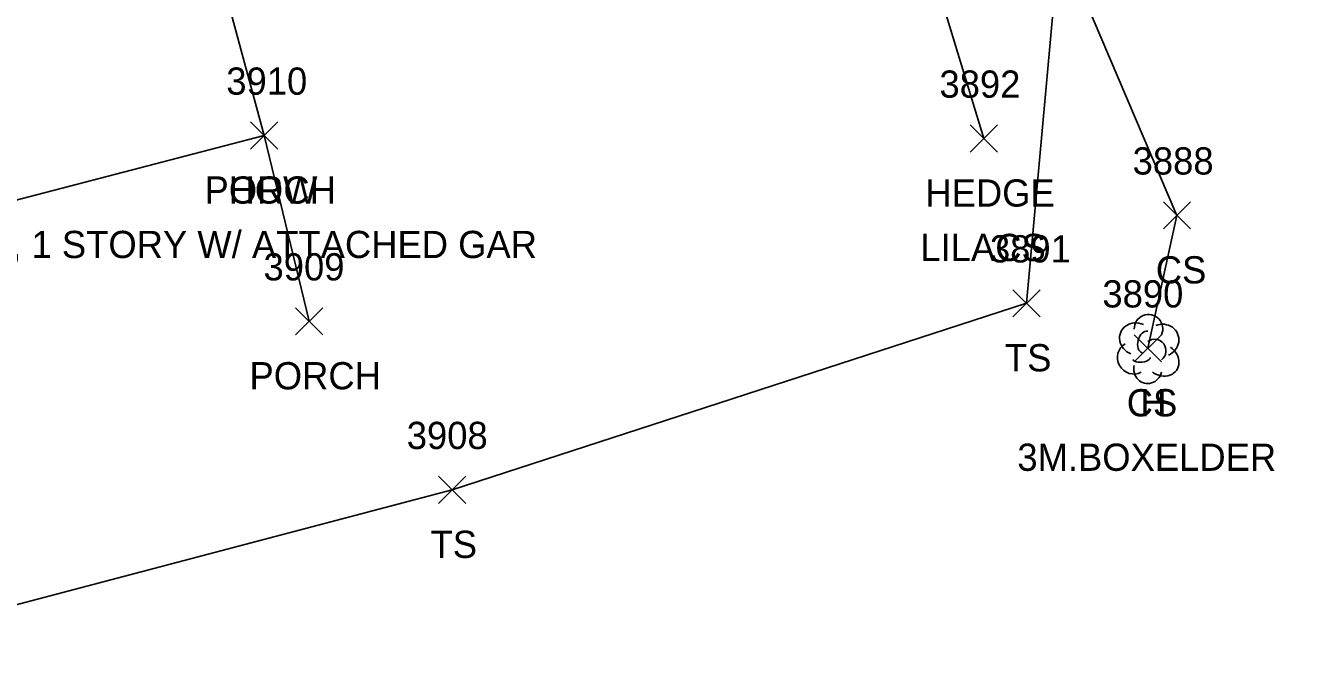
# Model space of a CAD drawing. Extents: x 1520648 to 1523413, y 732854 to 735518.
# Drawn here: x 1521101.5 to 1521194.8, y 733381.9 to 733427.9 of the extents above; entities that cross this region are included whole.
import ezdxf

# ---------------------------------------------------------------- set-up
doc = ezdxf.new("R2010")
doc.units = 0
for name, color, linetype in [('L_A', 7, 'Continuous'), ('L_C', 7, 'Continuous'), ('L_I', 7, 'Continuous'), ('L_TIC', 7, 'Continuous'), ('LAHR', 7, 'Continuous'), ('LBC', 7, 'Continuous'), ('LBF', 7, 'Continuous'), ('LELB', 7, 'Continuous'), ('LTD', 7, 'Continuous')]:
    doc.layers.add(name, color=color, linetype=linetype)

msp = doc.modelspace()

# ---------------------------------------------------------------- linework, layer by layer
at = {"layer": 'L_TIC'}
for points in [[(1521118.013, 733418.775), (1521120.013, 733420.775)], [(1521120.013, 733418.775), (1521118.013, 733420.775)], [(1521118.013, 733418.775), (1521120.013, 733420.775)], [(1521120.013, 733418.775), (1521118.013, 733420.775)], [(1521118.013, 733418.775), (1521120.013, 733420.775)], [(1521120.013, 733418.775), (1521118.013, 733420.775)], [(1521170.906, 733418.556), (1521172.906, 733420.556)], [(1521172.906, 733418.556), (1521170.906, 733420.556)], [(1521185.103, 733412.911), (1521187.103, 733414.911)], [(1521187.103, 733412.911), (1521185.103, 733414.911)], [(1521174.05, 733406.453), (1521176.05, 733408.453)], [(1521176.05, 733406.453), (1521174.05, 733408.453)], [(1521121.318, 733405.132), (1521123.318, 733407.132)], [(1521123.318, 733405.132), (1521121.318, 733407.132)], [(1521182.967, 733403.146), (1521184.967, 733405.146)], [(1521184.967, 733403.146), (1521182.967, 733405.146)], [(1521131.836, 733392.748), (1521133.836, 733394.748)], [(1521133.836, 733392.748), (1521131.836, 733394.748)]]:
    msp.add_lwpolyline(points, dxfattribs=at)
at = {"layer": 'LAHR'}
msp.add_lwpolyline([(1521171.906, 733419.556), (1521165.595, 733440.326)], dxfattribs=at)
at = {"layer": 'LBC'}
for points in [[(1521119.013, 733419.775), (1521112.234, 733444.881), (1521096.471, 733440.713), (1521093.138, 733452.827), (1521091.886, 733457.266), (1521088.382, 733469.903), (1521080.446, 733467.758), (1521080.092, 733468.783), (1521069.257, 733465.848), (1521065.514, 733464.895), (1521054.232, 733461.833), (1521062.279, 733432.129), (1521080.36, 733436.15)], [(1521119.013, 733419.775), (1521093.156, 733413.057), (1521090.415, 733422.521)]]:
    msp.add_lwpolyline(points, dxfattribs=at)
at = {"layer": 'LBF'}
msp.add_lwpolyline([(1521122.318, 733406.132), (1521119.013, 733419.775)], dxfattribs=at)
at = {"layer": 'LELB'}
for points in [[(1521156.262, 733492.333), (1521160.076, 733479.636), (1521169.187, 733456.994), (1521177.459, 733434.149), (1521186.103, 733413.911), (1521183.967, 733404.146)], [(1521252.104, 733415.19), (1521228.37, 733429.385), (1521182.522, 733453.142), (1521177.459, 733434.149), (1521175.05, 733407.453), (1521132.836, 733393.748), (1521088.037, 733381.942)]]:
    msp.add_lwpolyline(points, dxfattribs=at)
at = {"layer": 'LTD'}
msp.add_line((1521183.967, 733404.146), (1521183.967, 733404.146), dxfattribs=at)
msp.add_line((1521183.967, 733404.146), (1521183.967, 733404.146), dxfattribs=at)
msp.add_arc((1521184.014, 733405.58), 1.047, 335.52715, 180.95627, dxfattribs=at)
for centre, major_axis, ratio, start_param, end_param in [((1521183.175, 733404.812), (1.21, -0.512), 0.895232, 1.570796, 4.712389), ((1521183.759, 733404.604), (-0.208, -0.792), 0.645439, 3.141593, 6.283185), ((1521185.009, 733404.729), (-1.141, -0.483), 0.949671, 1.570796, 4.712389), ((1521182.884, 733403.437), (0.584, -1.042), 0.959034, 3.141593, 6.283185), ((1521184.467, 733403.979), (-0.5, 0.667), 0.989748, 3.141593, 6.283185), ((1521184.967, 733403.313), (-1.09, 0.792), 0.841452, 1.570796, 4.712389), ((1521183.968, 733402.646), (0.265, 1.061), 0.942809, 1.570796, 4.712389), ((1521183.509, 733403.396), (-0.625, -0.083), 0.423636, 0, 3.141593)]:
    msp.add_ellipse(centre, major_axis=major_axis, ratio=ratio, start_param=start_param, end_param=end_param, dxfattribs=at)

# ---------------------------------------------------------------- texts
at = {"layer": 'L_A'}
for s, p in [('PORCH', (1521114.635, 733414.775)), ('HOW', (1521116.399, 733414.775)), ('HOW', (1521116.399, 733414.775)), ('HEDGE', (1521167.607, 733414.556)), ('CS', (1521184.544, 733408.911)), ('TS', (1521173.46, 733402.453)), ('PORCH', (1521117.94, 733401.132)), ('CS', (1521182.408, 733399.146)), ('H', (1521183.4, 733399.146)), ('TS', (1521131.245, 733388.748))]:
    msp.add_text(s, height=2, dxfattribs=at).set_placement(p)
at = {"layer": 'L_C'}
for s, p in [('#172, 1 STORY W/ ATTACHED GAR', (1521094.486, 733410.775)), ('LILACS', (1521167.245, 733410.556)), ('3M.BOXELDER', (1521174.369, 733395.146))]:
    msp.add_text(s, height=2, dxfattribs=at).set_placement(p)
at = {"layer": 'L_I'}
for s, p in [('3910', (1521116.234, 733422.775)), ('3910', (1521116.234, 733422.775)), ('3910', (1521116.234, 733422.775)), ('3892', (1521168.646, 733422.556)), ('3888', (1521182.843, 733416.911)), ('3891', (1521172.357, 733410.453)), ('3909', (1521118.971, 733409.132)), ('3890', (1521180.621, 733407.146)), ('3890', (1521180.621, 733407.146)), ('3908', (1521129.497, 733396.748))]:
    msp.add_text(s, height=2, dxfattribs=at).set_placement(p)

doc.saveas('drawing.dxf')
